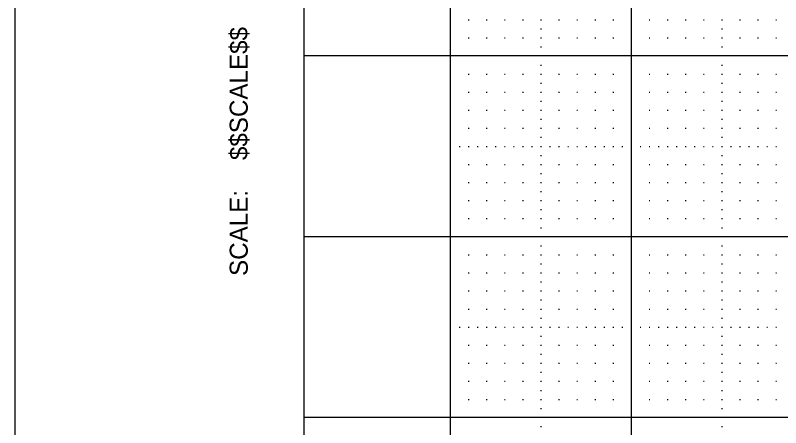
# Model space of a CAD drawing. Extents: x 0 to 34, y 0 to 22.
# Drawn here: x 0 to 4.231, y 3.215 to 5.497 of the extents above; entities that cross this region are included whole.
import ezdxf

# ---------------------------------------------------------------- set-up
doc = ezdxf.new("R2010")
doc.units = 0
for name, color, linetype in [('Level 1', 7, 'Continuous'), ('Level 4', 7, 'Continuous'), ('Level 5', 7, 'Continuous'), ('Level 63', 7, 'Continuous')]:
    doc.layers.add(name, color=color, linetype=linetype)

msp = doc.modelspace()

# ---------------------------------------------------------------- linework, layer by layer
at = {"layer": 'Level 1'}
msp.add_line((1.597, 0.726), (1.597, 21.272), dxfattribs=at)
at = {"layer": 'Level 4'}
for p, q in [((2.406, 1.272), (2.406, 21.272)), ((3.406, 1.272), (3.406, 21.272)), ((33.215, 5.272), (1.597, 5.272)), ((33.215, 4.272), (1.597, 4.272)), ((33.215, 3.272), (1.597, 3.272))]:
    msp.add_line(p, q, dxfattribs=at)
at = {"layer": 'Level 5'}
for p, q in [((2.5035, 5.472), (2.5085, 5.472)), ((2.6035, 5.472), (2.6085, 5.472)), ((2.7035, 5.472), (2.7085, 5.472)), ((2.8035, 5.472), (2.8085, 5.472)), ((2.9035, 5.472), (2.9085, 5.472)), ((3.0035, 5.472), (3.0085, 5.472)), ((3.1035, 5.472), (3.1085, 5.472)), ((3.2035, 5.472), (3.2085, 5.472)), ((3.3035, 5.472), (3.3085, 5.472)), ((3.5035, 5.472), (3.5085, 5.472)), ((3.6035, 5.472), (3.6085, 5.472)), ((3.7035, 5.472), (3.7085, 5.472)), ((3.8035, 5.472), (3.8085, 5.472)), ((3.9035, 5.472), (3.9085, 5.472)), ((4.0035, 5.472), (4.0085, 5.472)), ((4.1035, 5.472), (4.1085, 5.472)), ((4.2035, 5.472), (4.2085, 5.472)), ((2.9035, 5.422), (2.9085, 5.422)), ((3.9035, 5.422), (3.9085, 5.422)), ((2.5035, 5.372), (2.5085, 5.372)), ((2.6035, 5.372), (2.6085, 5.372)), ((2.7035, 5.372), (2.7085, 5.372)), ((2.8035, 5.372), (2.8085, 5.372)), ((2.9035, 5.372), (2.9085, 5.372)), ((3.0035, 5.372), (3.0085, 5.372)), ((3.1035, 5.372), (3.1085, 5.372)), ((3.2035, 5.372), (3.2085, 5.372)), ((3.3035, 5.372), (3.3085, 5.372)), ((3.5035, 5.372), (3.5085, 5.372)), ((3.6035, 5.372), (3.6085, 5.372)), ((3.7035, 5.372), (3.7085, 5.372)), ((3.8035, 5.372), (3.8085, 5.372)), ((3.9035, 5.372), (3.9085, 5.372)), ((4.0035, 5.372), (4.0085, 5.372)), ((4.1035, 5.372), (4.1085, 5.372)), ((4.2035, 5.372), (4.2085, 5.372)), ((2.9035, 5.322), (2.9085, 5.322)), ((3.9035, 5.322), (3.9085, 5.322)), ((2.9035, 5.222), (2.9085, 5.222)), ((3.9035, 5.222), (3.9085, 5.222)), ((2.5035, 5.172), (2.5085, 5.172)), ((2.6035, 5.172), (2.6085, 5.172)), ((2.7035, 5.172), (2.7085, 5.172)), ((2.8035, 5.172), (2.8085, 5.172)), ((2.9035, 5.172), (2.9085, 5.172)), ((3.0035, 5.172), (3.0085, 5.172)), ((3.1035, 5.172), (3.1085, 5.172)), ((3.2035, 5.172), (3.2085, 5.172)), ((3.3035, 5.172), (3.3085, 5.172)), ((3.5035, 5.172), (3.5085, 5.172)), ((3.6035, 5.172), (3.6085, 5.172)), ((3.7035, 5.172), (3.7085, 5.172)), ((3.8035, 5.172), (3.8085, 5.172)), ((3.9035, 5.172), (3.9085, 5.172)), ((4.0035, 5.172), (4.0085, 5.172)), ((4.1035, 5.172), (4.1085, 5.172)), ((4.2035, 5.172), (4.2085, 5.172)), ((2.9035, 5.122), (2.9085, 5.122)), ((3.9035, 5.122), (3.9085, 5.122)), ((2.5035, 5.072), (2.5085, 5.072)), ((2.6035, 5.072), (2.6085, 5.072)), ((2.7035, 5.072), (2.7085, 5.072)), ((2.8035, 5.072), (2.8085, 5.072)), ((2.9035, 5.072), (2.9085, 5.072)), ((3.0035, 5.072), (3.0085, 5.072)), ((3.1035, 5.072), (3.1085, 5.072)), ((3.2035, 5.072), (3.2085, 5.072)), ((3.3035, 5.072), (3.3085, 5.072)), ((3.5035, 5.072), (3.5085, 5.072)), ((3.6035, 5.072), (3.6085, 5.072)), ((3.7035, 5.072), (3.7085, 5.072)), ((3.8035, 5.072), (3.8085, 5.072)), ((3.9035, 5.072), (3.9085, 5.072)), ((4.0035, 5.072), (4.0085, 5.072)), ((4.1035, 5.072), (4.1085, 5.072)), ((4.2035, 5.072), (4.2085, 5.072)), ((2.9035, 5.022), (2.9085, 5.022)), ((3.9035, 5.022), (3.9085, 5.022)), ((2.5035, 4.972), (2.5085, 4.972)), ((2.6035, 4.972), (2.6085, 4.972)), ((2.7035, 4.972), (2.7085, 4.972)), ((2.8035, 4.972), (2.8085, 4.972)), ((2.9035, 4.972), (2.9085, 4.972)), ((3.0035, 4.972), (3.0085, 4.972)), ((3.1035, 4.972), (3.1085, 4.972)), ((3.2035, 4.972), (3.2085, 4.972)), ((3.3035, 4.972), (3.3085, 4.972)), ((3.5035, 4.972), (3.5085, 4.972)), ((3.6035, 4.972), (3.6085, 4.972)), ((3.7035, 4.972), (3.7085, 4.972)), ((3.8035, 4.972), (3.8085, 4.972)), ((3.9035, 4.972), (3.9085, 4.972)), ((4.0035, 4.972), (4.0085, 4.972)), ((4.1035, 4.972), (4.1085, 4.972)), ((4.2035, 4.972), (4.2085, 4.972)), ((2.9035, 4.922), (2.9085, 4.922)), ((3.9035, 4.922), (3.9085, 4.922)), ((2.5035, 4.872), (2.5085, 4.872)), ((2.6035, 4.872), (2.6085, 4.872)), ((2.7035, 4.872), (2.7085, 4.872)), ((2.8035, 4.872), (2.8085, 4.872)), ((2.9035, 4.872), (2.9085, 4.872)), ((3.0035, 4.872), (3.0085, 4.872)), ((3.1035, 4.872), (3.1085, 4.872)), ((3.2035, 4.872), (3.2085, 4.872)), ((3.3035, 4.872), (3.3085, 4.872)), ((3.5035, 4.872), (3.5085, 4.872)), ((3.6035, 4.872), (3.6085, 4.872)), ((3.7035, 4.872), (3.7085, 4.872)), ((3.8035, 4.872), (3.8085, 4.872)), ((3.9035, 4.872), (3.9085, 4.872)), ((4.0035, 4.872), (4.0085, 4.872)), ((4.1035, 4.872), (4.1085, 4.872)), ((4.2035, 4.872), (4.2085, 4.872)), ((2.9035, 4.822), (2.9085, 4.822)), ((3.9035, 4.822), (3.9085, 4.822)), ((2.4535, 4.772), (2.4585, 4.772)), ((2.5035, 4.772), (2.5085, 4.772)), ((2.5535, 4.772), (2.5585, 4.772)), ((2.6035, 4.772), (2.6085, 4.772)), ((2.6535, 4.772), (2.6585, 4.772)), ((2.7035, 4.772), (2.7085, 4.772)), ((2.7535, 4.772), (2.7585, 4.772)), ((2.8035, 4.772), (2.8085, 4.772)), ((2.8535, 4.772), (2.8585, 4.772)), ((2.9035, 4.772), (2.9085, 4.772)), ((2.9535, 4.772), (2.9585, 4.772)), ((3.0035, 4.772), (3.0085, 4.772)), ((3.0535, 4.772), (3.0585, 4.772)), ((3.1035, 4.772), (3.1085, 4.772)), ((3.1535, 4.772), (3.1585, 4.772)), ((3.2035, 4.772), (3.2085, 4.772)), ((3.2535, 4.772), (3.2585, 4.772)), ((3.3035, 4.772), (3.3085, 4.772)), ((3.3535, 4.772), (3.3585, 4.772)), ((3.4535, 4.772), (3.4585, 4.772)), ((3.5035, 4.772), (3.5085, 4.772)), ((3.5535, 4.772), (3.5585, 4.772)), ((3.6035, 4.772), (3.6085, 4.772)), ((3.6535, 4.772), (3.6585, 4.772)), ((3.7035, 4.772), (3.7085, 4.772)), ((3.7535, 4.772), (3.7585, 4.772)), ((3.8035, 4.772), (3.8085, 4.772)), ((3.8535, 4.772), (3.8585, 4.772)), ((3.9035, 4.772), (3.9085, 4.772)), ((3.9535, 4.772), (3.9585, 4.772)), ((4.0035, 4.772), (4.0085, 4.772)), ((4.0535, 4.772), (4.0585, 4.772)), ((4.1035, 4.772), (4.1085, 4.772)), ((4.1535, 4.772), (4.1585, 4.772)), ((4.2035, 4.772), (4.2085, 4.772)), ((2.9035, 4.722), (2.9085, 4.722)), ((3.9035, 4.722), (3.9085, 4.722)), ((2.5035, 4.672), (2.5085, 4.672)), ((2.6035, 4.672), (2.6085, 4.672)), ((2.7035, 4.672), (2.7085, 4.672)), ((2.8035, 4.672), (2.8085, 4.672)), ((2.9035, 4.672), (2.9085, 4.672)), ((3.0035, 4.672), (3.0085, 4.672)), ((3.1035, 4.672), (3.1085, 4.672)), ((3.2035, 4.672), (3.2085, 4.672)), ((3.3035, 4.672), (3.3085, 4.672)), ((3.5035, 4.672), (3.5085, 4.672)), ((3.6035, 4.672), (3.6085, 4.672)), ((3.7035, 4.672), (3.7085, 4.672)), ((3.8035, 4.672), (3.8085, 4.672)), ((3.9035, 4.672), (3.9085, 4.672)), ((4.0035, 4.672), (4.0085, 4.672)), ((4.1035, 4.672), (4.1085, 4.672)), ((4.2035, 4.672), (4.2085, 4.672)), ((2.9035, 4.622), (2.9085, 4.622)), ((3.9035, 4.622), (3.9085, 4.622)), ((2.5035, 4.572), (2.5085, 4.572)), ((2.6035, 4.572), (2.6085, 4.572)), ((2.7035, 4.572), (2.7085, 4.572)), ((2.8035, 4.572), (2.8085, 4.572)), ((2.9035, 4.572), (2.9085, 4.572)), ((3.0035, 4.572), (3.0085, 4.572)), ((3.1035, 4.572), (3.1085, 4.572)), ((3.2035, 4.572), (3.2085, 4.572)), ((3.3035, 4.572), (3.3085, 4.572)), ((3.5035, 4.572), (3.5085, 4.572)), ((3.6035, 4.572), (3.6085, 4.572)), ((3.7035, 4.572), (3.7085, 4.572)), ((3.8035, 4.572), (3.8085, 4.572)), ((3.9035, 4.572), (3.9085, 4.572)), ((4.0035, 4.572), (4.0085, 4.572)), ((4.1035, 4.572), (4.1085, 4.572)), ((4.2035, 4.572), (4.2085, 4.572)), ((2.9035, 4.522), (2.9085, 4.522)), ((3.9035, 4.522), (3.9085, 4.522)), ((2.5035, 4.472), (2.5085, 4.472)), ((2.6035, 4.472), (2.6085, 4.472)), ((2.7035, 4.472), (2.7085, 4.472)), ((2.8035, 4.472), (2.8085, 4.472)), ((2.9035, 4.472), (2.9085, 4.472)), ((3.0035, 4.472), (3.0085, 4.472)), ((3.1035, 4.472), (3.1085, 4.472)), ((3.2035, 4.472), (3.2085, 4.472)), ((3.3035, 4.472), (3.3085, 4.472)), ((3.5035, 4.472), (3.5085, 4.472)), ((3.6035, 4.472), (3.6085, 4.472)), ((3.7035, 4.472), (3.7085, 4.472)), ((3.8035, 4.472), (3.8085, 4.472)), ((3.9035, 4.472), (3.9085, 4.472)), ((4.0035, 4.472), (4.0085, 4.472)), ((4.1035, 4.472), (4.1085, 4.472)), ((4.2035, 4.472), (4.2085, 4.472)), ((2.9035, 4.422), (2.9085, 4.422)), ((3.9035, 4.422), (3.9085, 4.422)), ((2.5035, 4.372), (2.5085, 4.372)), ((2.6035, 4.372), (2.6085, 4.372)), ((2.7035, 4.372), (2.7085, 4.372)), ((2.8035, 4.372), (2.8085, 4.372)), ((2.9035, 4.372), (2.9085, 4.372)), ((3.0035, 4.372), (3.0085, 4.372)), ((3.1035, 4.372), (3.1085, 4.372)), ((3.2035, 4.372), (3.2085, 4.372)), ((3.3035, 4.372), (3.3085, 4.372)), ((3.5035, 4.372), (3.5085, 4.372)), ((3.6035, 4.372), (3.6085, 4.372)), ((3.7035, 4.372), (3.7085, 4.372)), ((3.8035, 4.372), (3.8085, 4.372)), ((3.9035, 4.372), (3.9085, 4.372)), ((4.0035, 4.372), (4.0085, 4.372)), ((4.1035, 4.372), (4.1085, 4.372)), ((4.2035, 4.372), (4.2085, 4.372)), ((2.9035, 4.322), (2.9085, 4.322)), ((3.9035, 4.322), (3.9085, 4.322)), ((2.9035, 4.222), (2.9085, 4.222)), ((3.9035, 4.222), (3.9085, 4.222)), ((2.5035, 4.172), (2.5085, 4.172)), ((2.6035, 4.172), (2.6085, 4.172)), ((2.7035, 4.172), (2.7085, 4.172)), ((2.8035, 4.172), (2.8085, 4.172)), ((2.9035, 4.172), (2.9085, 4.172)), ((3.0035, 4.172), (3.0085, 4.172)), ((3.1035, 4.172), (3.1085, 4.172)), ((3.2035, 4.172), (3.2085, 4.172)), ((3.3035, 4.172), (3.3085, 4.172)), ((3.5035, 4.172), (3.5085, 4.172)), ((3.6035, 4.172), (3.6085, 4.172)), ((3.7035, 4.172), (3.7085, 4.172)), ((3.8035, 4.172), (3.8085, 4.172)), ((3.9035, 4.172), (3.9085, 4.172)), ((4.0035, 4.172), (4.0085, 4.172)), ((4.1035, 4.172), (4.1085, 4.172)), ((4.2035, 4.172), (4.2085, 4.172)), ((2.9035, 4.122), (2.9085, 4.122)), ((3.9035, 4.122), (3.9085, 4.122)), ((2.5035, 4.072), (2.5085, 4.072)), ((2.6035, 4.072), (2.6085, 4.072)), ((2.7035, 4.072), (2.7085, 4.072)), ((2.8035, 4.072), (2.8085, 4.072)), ((2.9035, 4.072), (2.9085, 4.072)), ((3.0035, 4.072), (3.0085, 4.072)), ((3.1035, 4.072), (3.1085, 4.072)), ((3.2035, 4.072), (3.2085, 4.072)), ((3.3035, 4.072), (3.3085, 4.072)), ((3.5035, 4.072), (3.5085, 4.072)), ((3.6035, 4.072), (3.6085, 4.072)), ((3.7035, 4.072), (3.7085, 4.072)), ((3.8035, 4.072), (3.8085, 4.072)), ((3.9035, 4.072), (3.9085, 4.072)), ((4.0035, 4.072), (4.0085, 4.072)), ((4.1035, 4.072), (4.1085, 4.072)), ((4.2035, 4.072), (4.2085, 4.072)), ((2.9035, 4.022), (2.9085, 4.022)), ((3.9035, 4.022), (3.9085, 4.022)), ((2.5035, 3.972), (2.5085, 3.972)), ((2.6035, 3.972), (2.6085, 3.972)), ((2.7035, 3.972), (2.7085, 3.972)), ((2.8035, 3.972), (2.8085, 3.972)), ((2.9035, 3.972), (2.9085, 3.972)), ((3.0035, 3.972), (3.0085, 3.972)), ((3.1035, 3.972), (3.1085, 3.972)), ((3.2035, 3.972), (3.2085, 3.972)), ((3.3035, 3.972), (3.3085, 3.972)), ((3.5035, 3.972), (3.5085, 3.972)), ((3.6035, 3.972), (3.6085, 3.972)), ((3.7035, 3.972), (3.7085, 3.972)), ((3.8035, 3.972), (3.8085, 3.972)), ((3.9035, 3.972), (3.9085, 3.972)), ((4.0035, 3.972), (4.0085, 3.972)), ((4.1035, 3.972), (4.1085, 3.972)), ((4.2035, 3.972), (4.2085, 3.972)), ((2.9035, 3.922), (2.9085, 3.922)), ((3.9035, 3.922), (3.9085, 3.922)), ((2.5035, 3.872), (2.5085, 3.872)), ((2.6035, 3.872), (2.6085, 3.872)), ((2.7035, 3.872), (2.7085, 3.872)), ((2.8035, 3.872), (2.8085, 3.872)), ((2.9035, 3.872), (2.9085, 3.872)), ((3.0035, 3.872), (3.0085, 3.872)), ((3.1035, 3.872), (3.1085, 3.872)), ((3.2035, 3.872), (3.2085, 3.872)), ((3.3035, 3.872), (3.3085, 3.872)), ((3.5035, 3.872), (3.5085, 3.872)), ((3.6035, 3.872), (3.6085, 3.872)), ((3.7035, 3.872), (3.7085, 3.872)), ((3.8035, 3.872), (3.8085, 3.872)), ((3.9035, 3.872), (3.9085, 3.872)), ((4.0035, 3.872), (4.0085, 3.872)), ((4.1035, 3.872), (4.1085, 3.872)), ((4.2035, 3.872), (4.2085, 3.872)), ((2.9035, 3.822), (2.9085, 3.822)), ((3.9035, 3.822), (3.9085, 3.822)), ((2.4535, 3.772), (2.4585, 3.772)), ((2.5035, 3.772), (2.5085, 3.772)), ((2.5535, 3.772), (2.5585, 3.772)), ((2.6035, 3.772), (2.6085, 3.772)), ((2.6535, 3.772), (2.6585, 3.772)), ((2.7035, 3.772), (2.7085, 3.772)), ((2.7535, 3.772), (2.7585, 3.772)), ((2.8035, 3.772), (2.8085, 3.772)), ((2.8535, 3.772), (2.8585, 3.772)), ((2.9035, 3.772), (2.9085, 3.772)), ((2.9535, 3.772), (2.9585, 3.772)), ((3.0035, 3.772), (3.0085, 3.772)), ((3.0535, 3.772), (3.0585, 3.772)), ((3.1035, 3.772), (3.1085, 3.772)), ((3.1535, 3.772), (3.1585, 3.772)), ((3.2035, 3.772), (3.2085, 3.772)), ((3.2535, 3.772), (3.2585, 3.772)), ((3.3035, 3.772), (3.3085, 3.772)), ((3.3535, 3.772), (3.3585, 3.772)), ((3.4535, 3.772), (3.4585, 3.772)), ((3.5035, 3.772), (3.5085, 3.772)), ((3.5535, 3.772), (3.5585, 3.772)), ((3.6035, 3.772), (3.6085, 3.772)), ((3.6535, 3.772), (3.6585, 3.772)), ((3.7035, 3.772), (3.7085, 3.772)), ((3.7535, 3.772), (3.7585, 3.772)), ((3.8035, 3.772), (3.8085, 3.772)), ((3.8535, 3.772), (3.8585, 3.772)), ((3.9035, 3.772), (3.9085, 3.772)), ((3.9535, 3.772), (3.9585, 3.772)), ((4.0035, 3.772), (4.0085, 3.772)), ((4.0535, 3.772), (4.0585, 3.772)), ((4.1035, 3.772), (4.1085, 3.772)), ((4.1535, 3.772), (4.1585, 3.772)), ((4.2035, 3.772), (4.2085, 3.772)), ((2.9035, 3.722), (2.9085, 3.722)), ((3.9035, 3.722), (3.9085, 3.722)), ((2.5035, 3.672), (2.5085, 3.672)), ((2.6035, 3.672), (2.6085, 3.672)), ((2.7035, 3.672), (2.7085, 3.672)), ((2.8035, 3.672), (2.8085, 3.672)), ((2.9035, 3.672), (2.9085, 3.672)), ((3.0035, 3.672), (3.0085, 3.672)), ((3.1035, 3.672), (3.1085, 3.672)), ((3.2035, 3.672), (3.2085, 3.672)), ((3.3035, 3.672), (3.3085, 3.672)), ((3.5035, 3.672), (3.5085, 3.672)), ((3.6035, 3.672), (3.6085, 3.672)), ((3.7035, 3.672), (3.7085, 3.672)), ((3.8035, 3.672), (3.8085, 3.672)), ((3.9035, 3.672), (3.9085, 3.672)), ((4.0035, 3.672), (4.0085, 3.672)), ((4.1035, 3.672), (4.1085, 3.672)), ((4.2035, 3.672), (4.2085, 3.672)), ((2.9035, 3.622), (2.9085, 3.622)), ((3.9035, 3.622), (3.9085, 3.622)), ((2.5035, 3.572), (2.5085, 3.572)), ((2.6035, 3.572), (2.6085, 3.572)), ((2.7035, 3.572), (2.7085, 3.572)), ((2.8035, 3.572), (2.8085, 3.572)), ((2.9035, 3.572), (2.9085, 3.572)), ((3.0035, 3.572), (3.0085, 3.572)), ((3.1035, 3.572), (3.1085, 3.572)), ((3.2035, 3.572), (3.2085, 3.572)), ((3.3035, 3.572), (3.3085, 3.572)), ((3.5035, 3.572), (3.5085, 3.572)), ((3.6035, 3.572), (3.6085, 3.572)), ((3.7035, 3.572), (3.7085, 3.572)), ((3.8035, 3.572), (3.8085, 3.572)), ((3.9035, 3.572), (3.9085, 3.572)), ((4.0035, 3.572), (4.0085, 3.572)), ((4.1035, 3.572), (4.1085, 3.572)), ((4.2035, 3.572), (4.2085, 3.572)), ((2.9035, 3.522), (2.9085, 3.522)), ((3.9035, 3.522), (3.9085, 3.522)), ((2.5035, 3.472), (2.5085, 3.472)), ((2.6035, 3.472), (2.6085, 3.472)), ((2.7035, 3.472), (2.7085, 3.472)), ((2.8035, 3.472), (2.8085, 3.472)), ((2.9035, 3.472), (2.9085, 3.472)), ((3.0035, 3.472), (3.0085, 3.472)), ((3.1035, 3.472), (3.1085, 3.472)), ((3.2035, 3.472), (3.2085, 3.472)), ((3.3035, 3.472), (3.3085, 3.472)), ((3.5035, 3.472), (3.5085, 3.472)), ((3.6035, 3.472), (3.6085, 3.472)), ((3.7035, 3.472), (3.7085, 3.472)), ((3.8035, 3.472), (3.8085, 3.472)), ((3.9035, 3.472), (3.9085, 3.472)), ((4.0035, 3.472), (4.0085, 3.472)), ((4.1035, 3.472), (4.1085, 3.472)), ((4.2035, 3.472), (4.2085, 3.472)), ((2.9035, 3.422), (2.9085, 3.422)), ((3.9035, 3.422), (3.9085, 3.422)), ((2.5035, 3.372), (2.5085, 3.372)), ((2.6035, 3.372), (2.6085, 3.372)), ((2.7035, 3.372), (2.7085, 3.372)), ((2.8035, 3.372), (2.8085, 3.372)), ((2.9035, 3.372), (2.9085, 3.372)), ((3.0035, 3.372), (3.0085, 3.372)), ((3.1035, 3.372), (3.1085, 3.372)), ((3.2035, 3.372), (3.2085, 3.372)), ((3.3035, 3.372), (3.3085, 3.372)), ((3.5035, 3.372), (3.5085, 3.372)), ((3.6035, 3.372), (3.6085, 3.372)), ((3.7035, 3.372), (3.7085, 3.372)), ((3.8035, 3.372), (3.8085, 3.372)), ((3.9035, 3.372), (3.9085, 3.372)), ((4.0035, 3.372), (4.0085, 3.372)), ((4.1035, 3.372), (4.1085, 3.372)), ((4.2035, 3.372), (4.2085, 3.372)), ((2.9035, 3.322), (2.9085, 3.322)), ((3.9035, 3.322), (3.9085, 3.322)), ((2.9035, 3.222), (2.9085, 3.222)), ((3.9035, 3.222), (3.9085, 3.222))]:
    msp.add_line(p, q, dxfattribs=at)
at = {"layer": 'Level 63'}
msp.add_lwpolyline([(0, 22), (34, 22), (34, 0), (0, 0)], close=True, dxfattribs=at)

# ---------------------------------------------------------------- texts
at = {"layer": 'Level 1'}
for s, p in [('$$SCALE$$', (1.285, 4.696)), ('SCALE:', (1.285, 4.055))]:
    msp.add_text(s, height=0.1, rotation=90, dxfattribs=at).set_placement(p)

doc.saveas('drawing.dxf')
